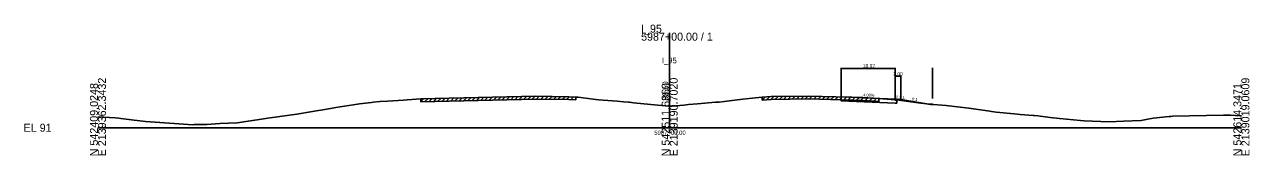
# Model space of a CAD drawing. Extents: x -12534 to 3403, y -1332 to 21983.
# Drawn here: x -25.7 to 402.8, y 16990.3 to 17036 of the extents above; entities that cross this region are included whole.
import ezdxf

# ---------------------------------------------------------------- set-up
doc = ezdxf.new("R2010")
doc.units = 0
for name, color, linetype in [('RD_GPK_XS_Cell', 7, 'Continuous'), ('RD_XD_TX_Width', 7, 'Continuous'), ('RD_XS_Base', 7, 'Continuous'), ('RD_XS_EarthShd', 7, 'Continuous'), ('RD_XS_EwShp', 7, 'Continuous'), ('RD_XS_ExGround', 7, 'Continuous'), ('RD_XS_ExPaveRet', 7, 'Continuous'), ('RD_XS_OSBase', 7, 'Continuous'), ('RD_XS_Pave', 7, 'Continuous'), ('RD_XS_TieSlope', 7, 'Continuous'), ('RD_XS_TX_Baseline', 7, 'Continuous'), ('RD_XS_TX_Elev_EX', 7, 'Continuous'), ('RD_XS_TX_ShdSlope', 7, 'Continuous'), ('RD_XS_TX_Slope', 7, 'Continuous'), ('RD_XS_TX_Station', 7, 'Continuous')]:
    doc.layers.add(name, color=color, linetype=linetype)

msp = doc.modelspace()

# ---------------------------------------------------------------- linework, layer by layer
at = {"layer": 'RD_GPK_XS_Cell'}
for p, q in [((200, 17000), (200, 17033.2)), ((0, 17000), (200, 17000)), ((200, 17000), (400, 17000))]:
    msp.add_line(p, q, dxfattribs=at)
at = {"layer": 'RD_XD_TX_Width'}
for p, q in [((260, 17020.91), (260, 17010.96)), ((260, 17020.71), (278.92, 17020.71)), ((278.92, 17020.91), (278.92, 17010.21)), ((278.92, 17018.16), (278.92, 17010.21)), ((278.92, 17017.96), (280.92, 17017.96)), ((280.92, 17018.16), (280.92, 17010.05)), ((291.92, 17020.91), (291.92, 17010.21))]:
    msp.add_line(p, q, dxfattribs=at)
at = {"layer": 'RD_XS_Base'}
msp.add_line((260, 17009.36), (278.92, 17008.61), dxfattribs=at)
at = {"layer": 'RD_XS_EarthShd'}
msp.add_line((278.92, 17010.01), (280.92, 17009.85), dxfattribs=at)
at = {"layer": 'RD_XS_EwShp'}
for points in [[(279.42, 17008.59), (279.42, 17009.59), (278.92, 17009.61), (278.92, 17009.78), (273.2, 17010.21), (267.62, 17010.56), (260, 17010.77), (260, 17010.36), (260, 17009.36), (278.92, 17008.61)], [(278.92, 17010.01), (280.92, 17009.85), (289.26, 17008.46), (286.94, 17008.73), (285.34, 17008.95), (284.42, 17009.06), (280.34, 17009.67), (279.95, 17009.7), (278.92, 17009.78)], [(291.92, 17008.01), (291.92, 17008.17), (290.74, 17008.28), (289.26, 17008.46)]]:
    msp.add_lwpolyline(points, close=True, dxfattribs=at)
at = {"layer": 'RD_XS_ExGround'}
msp.add_lwpolyline([(0, 17003.83), (6.16, 17003.45), (7.36, 17003.3), (7.99, 17003.25), (11.78, 17002.76), (16.61, 17002.13), (28.28, 17001.3), (33.25, 17001.05), (33.71, 17001.07), (35.2, 17001.09), (38.1, 17001.17), (42.69, 17001.45), (48.69, 17001.68), (58.72, 17003.19), (59.33, 17003.28), (60.28, 17003.42), (69.53, 17004.78), (75.1, 17005.69), (80.03, 17006.47), (83.2, 17007.01), (90.81, 17008.26), (91.52, 17008.35), (95.64, 17008.84), (96.26, 17008.92), (98.75, 17009.12), (101.29, 17009.33), (106.93, 17009.64), (108.2, 17009.77), (112.9, 17010.08), (117.82, 17010.2), (153.2, 17010.99), (164.73, 17010.81), (167.17, 17010.71), (167.99, 17010.62), (173.24, 17009.96), (175.06, 17009.76), (181.65, 17009.25), (183.86, 17009.04), (185.62, 17008.9), (185.97, 17008.87), (187.36, 17008.73), (195.86, 17007.86), (200, 17007.5), (200.88, 17007.51), (204.98, 17007.89), (206.58, 17008.06), (209.75, 17008.38), (216.07, 17008.88), (216.65, 17008.91), (217.31, 17008.96), (219.07, 17009.17), (225.62, 17009.98), (227.78, 17010.21), (231.15, 17010.54), (232.41, 17010.68), (235.5, 17010.9), (248.66, 17011.07), (267.62, 17010.56), (273.2, 17010.21), (279.95, 17009.7), (280.34, 17009.67), (284.42, 17009.06), (285.34, 17008.95), (286.94, 17008.73), (290.74, 17008.28), (296.78, 17007.71), (301.57, 17007.18), (304.68, 17006.79), (312.03, 17005.73), (312.57, 17005.66), (314.21, 17005.49), (320.5, 17004.8), (322.57, 17004.59), (327.2, 17004.29), (327.55, 17004.27), (328.76, 17004.12), (333.11, 17003.6), (336.33, 17003.19), (343.69, 17002.48), (345.04, 17002.43), (353.73, 17002.1), (358.75, 17002.33), (364.96, 17002.53), (367.32, 17003.01), (369.11, 17003.31), (374.69, 17003.9), (375.36, 17003.94), (375.92, 17004), (393.77, 17004.42), (396.23, 17004.35), (399.65, 17004.21), (400, 17004.21)], dxfattribs=at)
at = {"layer": 'RD_XS_ExPaveRet'}
for p, q in [((112.9, 17009.08), (113.93, 17010.1)), ((112.9, 17009.08), (112.9, 17010.08)), ((112.9, 17009.08), (117.82, 17009.2)), ((114.4, 17009.11), (115.43, 17010.14)), ((115.9, 17009.15), (116.93, 17010.18)), ((117.4, 17009.19), (118.42, 17010.21)), ((117.82, 17009.2), (153.2, 17009.99)), ((118.9, 17009.22), (119.92, 17010.25)), ((120.4, 17009.26), (121.42, 17010.28)), ((121.9, 17009.29), (122.92, 17010.31)), ((123.4, 17009.33), (124.42, 17010.35)), ((124.9, 17009.36), (125.92, 17010.38)), ((126.4, 17009.39), (127.42, 17010.42)), ((127.9, 17009.43), (128.92, 17010.45)), ((129.4, 17009.46), (130.42, 17010.48)), ((130.9, 17009.49), (131.92, 17010.52)), ((132.4, 17009.53), (133.42, 17010.55)), ((133.9, 17009.56), (134.92, 17010.58)), ((135.4, 17009.59), (136.42, 17010.62)), ((136.9, 17009.63), (137.92, 17010.65)), ((138.4, 17009.66), (139.42, 17010.68)), ((139.9, 17009.69), (140.92, 17010.72)), ((141.4, 17009.73), (142.42, 17010.75)), ((142.9, 17009.76), (143.92, 17010.78)), ((144.4, 17009.79), (145.42, 17010.82)), ((145.9, 17009.83), (146.92, 17010.85)), ((147.4, 17009.86), (148.42, 17010.88)), ((148.9, 17009.89), (149.92, 17010.92)), ((150.4, 17009.93), (151.42, 17010.95)), ((151.9, 17009.96), (152.92, 17010.98)), ((153.2, 17009.99), (164.73, 17009.81)), ((153.4, 17009.99), (154.39, 17010.97)), ((154.9, 17009.96), (155.89, 17010.95)), ((156.4, 17009.94), (157.39, 17010.93)), ((157.9, 17009.92), (158.89, 17010.9)), ((159.4, 17009.9), (160.39, 17010.88)), ((160.9, 17009.87), (161.89, 17010.86)), ((162.4, 17009.85), (163.39, 17010.83)), ((163.9, 17009.83), (164.88, 17010.81)), ((164.73, 17009.81), (167.17, 17009.71)), ((165.4, 17009.78), (166.36, 17010.74)), ((167.17, 17010.71), (167.17, 17009.71)), ((232.41, 17009.68), (233.49, 17010.75)), ((232.41, 17009.68), (232.41, 17010.68)), ((232.41, 17009.68), (235.5, 17009.9)), ((233.91, 17009.78), (234.99, 17010.86)), ((235.41, 17009.89), (236.43, 17010.91)), ((235.5, 17009.9), (248.66, 17010.07)), ((236.91, 17009.92), (237.92, 17010.93)), ((238.41, 17009.94), (239.42, 17010.95)), ((239.91, 17009.96), (240.92, 17010.97)), ((241.41, 17009.98), (242.42, 17010.99)), ((242.91, 17009.99), (243.92, 17011.01)), ((244.41, 17010.01), (245.42, 17011.03)), ((245.91, 17010.03), (246.92, 17011.05)), ((247.41, 17010.05), (248.42, 17011.07)), ((248.66, 17010.07), (267.62, 17009.56)), ((248.91, 17010.06), (249.89, 17011.04)), ((250.41, 17010.02), (251.39, 17011)), ((251.91, 17009.98), (252.89, 17010.96)), ((253.41, 17009.94), (254.39, 17010.92)), ((254.91, 17009.9), (255.89, 17010.88)), ((256.41, 17009.86), (257.39, 17010.84)), ((257.91, 17009.82), (258.89, 17010.8)), ((259.41, 17009.78), (260.39, 17010.76)), ((260.91, 17009.74), (261.89, 17010.72)), ((262.41, 17009.7), (263.39, 17010.68)), ((263.91, 17009.66), (264.89, 17010.64)), ((265.41, 17009.62), (266.39, 17010.6)), ((266.91, 17009.58), (267.88, 17010.55)), ((267.62, 17009.56), (273.2, 17009.21)), ((268.41, 17009.51), (269.35, 17010.45)), ((269.91, 17009.42), (270.85, 17010.36)), ((271.41, 17009.33), (272.35, 17010.27)), ((273.2, 17010.21), (273.2, 17009.21))]:
    msp.add_line(p, q, dxfattribs=at)
at = {"layer": 'RD_XS_OSBase'}
for p, q in [((260, 17010.36), (260, 17010.76)), ((260, 17009.36), (260, 17010.36)), ((278.92, 17009.61), (278.92, 17010.01)), ((279.42, 17009.59), (278.92, 17009.61)), ((278.92, 17008.61), (279.42, 17008.59)), ((279.42, 17008.59), (279.42, 17009.59))]:
    msp.add_line(p, q, dxfattribs=at)
at = {"layer": 'RD_XS_Pave'}
msp.add_line((260, 17010.76), (278.92, 17010.01), dxfattribs=at)
at = {"layer": 'RD_XS_TieSlope'}
for p, q in [((280.92, 17009.85), (291.92, 17008.01)), ((291.92, 17008.01), (291.92, 17008.17))]:
    msp.add_line(p, q, dxfattribs=at)

# ---------------------------------------------------------------- texts
at = {"layer": 'RD_GPK_XS_Cell'}
for s, p in [('I_95', (190, 17033.2)), ('5987+00.00 / 1', (190, 17030.4)), ('EL 91', (-26, 16998.6))]:
    msp.add_text(s, height=2.8, dxfattribs=at).set_placement(p)
for s, p in [('E 2139362.3432', (2.8, 16990)), ('E 2139190.7020', (202.8, 16990)), ('E 2139019.0609', (402.8, 16990)), ('N 542409.0248', (0, 16990)), ('N 542511.6860', (200, 16990)), ('N 542614.3471', (400, 16990))]:
    msp.add_text(s, height=2.8, rotation=90, dxfattribs=at).set_placement(p)
at = {"layer": 'RD_XD_TX_Width'}
for s, p in [('18.92', (267.54, 17020.96)), ('2.00', (278.23, 17018.21))]:
    msp.add_text(s, height=1.25, dxfattribs=at).set_placement(p)
at = {"layer": 'RD_XS_TX_Baseline'}
msp.add_text('I_95', height=2, dxfattribs=at).set_placement((197.28, 17022.5))
at = {"layer": 'RD_XS_TX_Elev_EX'}
msp.add_text('98.50', height=2, rotation=90, dxfattribs=at).set_placement((199.5, 17009.5))
at = {"layer": 'RD_XS_TX_ShdSlope'}
msp.add_text('12.5:1', height=1, rotation=355.4279, dxfattribs=at).set_placement((278.43, 17010.3))
msp.add_text('12.5:1', height=1, rotation=355.4279, dxfattribs=at).set_placement((278.43, 17010.3))
at = {"layer": 'RD_XS_TX_Slope'}
for s, rotation, p in [('4.00%', 357.7094, (267.68, 17010.96)), ('6:1', 350.5415, (284.73, 17009.62))]:
    msp.add_text(s, height=1, rotation=rotation, dxfattribs=at).set_placement(p)
at = {"layer": 'RD_XS_TX_Station'}
msp.add_text('5987+00.00', height=1.5, dxfattribs=at).set_placement((194.6, 16997.5))

doc.saveas('drawing.dxf')
